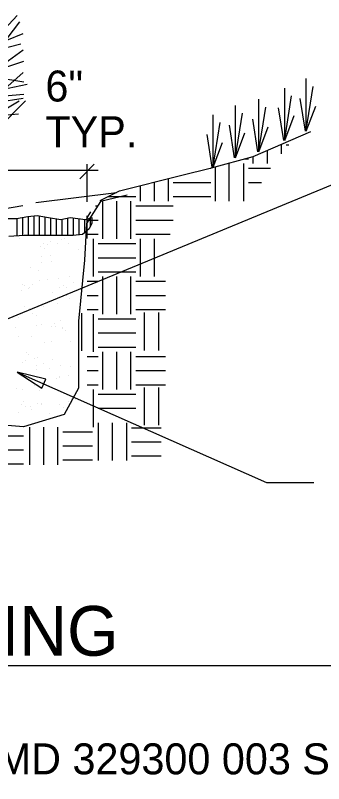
# Model space of a CAD drawing. Extents: x 10082 to 10186, y 10014 to 10052.
# Drawn here: x 10140.43 to 10147.41, y 10014.37 to 10031.75 of the extents above; entities that cross this region are included whole.
import ezdxf

# ---------------------------------------------------------------- set-up
doc = ezdxf.new("R2010")
doc.units = 0
for name, color, linetype in [('Default', 7, 'Continuous'), ('G-ANNO-CELL', 7, 'Continuous'), ('G-ANNO-TEXT', 7, 'Continuous'), ('G-DETL-GRID', 7, 'Continuous'), ('G-DETL-LINE', 7, 'Continuous'), ('G-DETL-OTLN', 7, 'Continuous'), ('G-DETL-PATT', 7, 'Continuous'), ('G-DETL-TEXT', 7, 'Continuous')]:
    doc.layers.add(name, color=color, linetype=linetype)

msp = doc.modelspace()

# ---------------------------------------------------------------- linework, layer by layer
at = {"layer": 'Default'}
for p, q in [((10148.734, 10028.388), (10138.509, 10024.167)), ((10141.886, 10028.058), (10142.213, 10028.385)), ((10142.05, 10027.536), (10142.05, 10028.385)), ((10139.707, 10028.252), (10142.301, 10028.252)), ((10144.838, 10028.297), (10144.857, 10028.297)), ((10140.472, 10023.683), (10146.119, 10021.186)), ((10146.119, 10021.186), (10147.188, 10021.186))]:
    msp.add_line(p, q, dxfattribs=at)
msp.add_lwpolyline([(10141.028, 10023.323), (10141.115, 10023.523), (10140.472, 10023.683)], close=True, dxfattribs=at)
at = {"layer": 'G-ANNO-TEXT'}
msp.add_line((10122.114, 10017.044), (10151.008, 10017.044), dxfattribs=at)
at = {"layer": 'G-DETL-LINE'}
for p, q in [((10140.231, 10031.197), (10140.603, 10031.347)), ((10139.716, 10030.903), (10140.549, 10031.107)), ((10139.938, 10030.496), (10140.603, 10030.975)), ((10139.716, 10030.4), (10140.621, 10030.25)), ((10147.016, 10029.175), (10147.016, 10030.324)), ((10140.267, 10030.106), (10140.698, 10030.196)), ((10146.527, 10028.961), (10146.527, 10030.111)), ((10147.016, 10029.157), (10147.173, 10030.149)), ((10146.527, 10028.944), (10146.685, 10029.935)), ((10139.77, 10029.752), (10140.603, 10029.884)), ((10139.83, 10028.991), (10140.657, 10029.818)), ((10139.991, 10029.513), (10140.513, 10029.824)), ((10145.941, 10028.707), (10145.941, 10029.856)), ((10146.996, 10029.137), (10146.878, 10029.877)), ((10145.412, 10028.569), (10145.412, 10029.719)), ((10145.941, 10028.689), (10146.099, 10029.681)), ((10146.507, 10028.923), (10146.39, 10029.663)), ((10147.016, 10029.137), (10147.23, 10029.701)), ((10144.907, 10028.356), (10144.907, 10029.505)), ((10145.412, 10028.552), (10145.57, 10029.543)), ((10145.921, 10028.669), (10145.804, 10029.409)), ((10146.527, 10028.923), (10146.741, 10029.488)), ((10144.907, 10028.338), (10145.065, 10029.33)), ((10145.392, 10028.531), (10145.275, 10029.271)), ((10145.941, 10028.669), (10146.155, 10029.233)), ((10144.887, 10028.318), (10144.77, 10029.058)), ((10145.412, 10028.531), (10145.626, 10029.096)), ((10144.907, 10028.318), (10145.121, 10028.882)), ((10142.051, 10027.178), (10142.134, 10027.311)), ((10142.246, 10027.445), (10142.301, 10027.445)), ((10142.054, 10026.71), (10142.054, 10027.222))]:
    msp.add_line(p, q, dxfattribs=at)
for points in [[(10137.841, 10030.418), (10139.692, 10030.921), (10140.471, 10031.755)], [(10137.176, 10028.158), (10137.158, 10028.715), (10137.859, 10029.231), (10139.141, 10029.788), (10140.531, 10031.605)], [(10138.098, 10028.733), (10138.302, 10028.937), (10139.063, 10030.196), (10140.621, 10030.718)], [(10138.098, 10028.751), (10138.955, 10029.009), (10140.603, 10030.46)], [(10139.123, 10029.842), (10140.621, 10029.974)], [(10139.452, 10029.435), (10140.495, 10029.53)], [(10140.89, 10027.523), (10142.717, 10027.745)], [(10137.607, 10026.942), (10140.597, 10027.451)]]:
    msp.add_lwpolyline(points, dxfattribs=at)
at = {"layer": 'G-DETL-OTLN'}
for p, q in [((10142.351, 10027.57), (10142.784, 10027.787)), ((10140.153, 10027.159), (10140.452, 10027.159)), ((10140.452, 10027.159), (10140.709, 10027.205)), ((10140.709, 10027.205), (10140.923, 10027.224)), ((10140.923, 10027.224), (10141.18, 10027.182)), ((10141.18, 10027.182), (10141.457, 10027.14)), ((10141.457, 10027.14), (10141.672, 10027.182)), ((10141.672, 10027.182), (10142.013, 10027.14)), ((10142.013, 10027.14), (10142.163, 10027.182)), ((10142.163, 10027.182), (10142.163, 10027.055)), ((10142.163, 10027.055), (10142.098, 10026.925)), ((10141.948, 10026.798), (10141.737, 10026.775)), ((10142.098, 10026.925), (10141.948, 10026.798)), ((10140.624, 10026.775), (10140.283, 10026.755)), ((10140.988, 10026.775), (10140.624, 10026.775)), ((10141.737, 10026.775), (10140.988, 10026.775))]:
    msp.add_line(p, q, dxfattribs=at)
for points in [[(10145.817, 10028.563), (10147.117, 10029.129)], [(10144.867, 10028.304), (10145.817, 10028.563)], [(10144.168, 10028.129), (10144.867, 10028.304)], [(10142.784, 10027.787), (10144.168, 10028.129)], [(10142.956, 10027.686), (10142.357, 10027.547), (10142.04, 10027.044), (10141.992, 10026.215), (10141.854, 10024.835), (10141.854, 10023.321), (10141.53, 10022.722), (10140.614, 10022.448), (10138.96, 10022.583), (10137.624, 10022.539), (10136.198, 10022.539), (10134.778, 10022.631), (10133.4, 10022.539), (10132.292, 10022.539), (10131.603, 10023.091), (10131.513, 10024.284), (10131.375, 10025.343), (10131.148, 10025.251)]]:
    msp.add_lwpolyline(points, dxfattribs=at)
at = {"layer": 'G-DETL-PATT'}
for p, q in [((10146.135, 10028.403), (10146.135, 10028.701)), ((10146.455, 10028.619), (10146.455, 10028.841)), ((10146.561, 10028.829), (10146.619, 10028.829)), ((10145.816, 10028.403), (10145.816, 10028.562)), ((10145.267, 10027.551), (10145.267, 10028.403)), ((10145.603, 10027.551), (10145.603, 10028.403)), ((10145.623, 10028.51), (10145.709, 10028.51)), ((10144.964, 10027.551), (10144.964, 10028.33)), ((10145.709, 10028.297), (10146.204, 10028.297)), ((10143.898, 10027.551), (10143.898, 10028.063)), ((10143.259, 10027.551), (10143.259, 10027.904)), ((10143.579, 10027.551), (10143.579, 10027.983)), ((10144.005, 10027.977), (10144.857, 10027.977)), ((10145.709, 10027.977), (10146.004, 10027.977)), ((10142.527, 10027.658), (10143.153, 10027.658)), ((10144.005, 10027.658), (10144.857, 10027.658)), ((10142.407, 10026.699), (10142.407, 10027.551)), ((10142.727, 10026.699), (10142.727, 10027.551)), ((10143.046, 10026.699), (10143.046, 10027.551)), ((10143.153, 10027.445), (10144.005, 10027.445)), ((10140.466, 10026.766), (10140.466, 10027.162)), ((10140.594, 10026.773), (10140.594, 10027.184)), ((10140.722, 10026.775), (10140.722, 10027.206)), ((10140.85, 10026.775), (10140.85, 10027.218)), ((10140.977, 10026.775), (10140.977, 10027.215)), ((10141.105, 10026.775), (10141.105, 10027.194)), ((10141.233, 10026.775), (10141.233, 10027.174)), ((10141.361, 10026.775), (10141.361, 10027.154)), ((10141.489, 10026.775), (10141.489, 10027.146)), ((10141.616, 10026.775), (10141.616, 10027.171)), ((10141.744, 10026.776), (10141.744, 10027.173)), ((10141.872, 10026.79), (10141.872, 10027.157)), ((10142, 10026.842), (10142, 10027.141)), ((10142.128, 10026.984), (10142.128, 10027.172)), ((10142.054, 10027.125), (10142.301, 10027.125)), ((10143.153, 10027.125), (10144.005, 10027.125)), ((10142.054, 10026.806), (10142.301, 10026.806)), ((10143.153, 10026.806), (10143.932, 10026.806)), ((10140.528, 10026.71), (10140.528, 10026.71)), ((10141.221, 10026.647), (10141.221, 10026.647)), ((10141.466, 10026.674), (10141.466, 10026.674)), ((10141.55, 10026.71), (10141.55, 10026.71)), ((10142.194, 10025.847), (10142.194, 10026.699)), ((10143.259, 10025.847), (10143.259, 10026.699)), ((10143.579, 10025.847), (10143.579, 10026.699)), ((10140.999, 10026.53), (10140.999, 10026.53)), ((10141.068, 10026.584), (10141.068, 10026.584)), ((10141.082, 10026.489), (10141.082, 10026.489)), ((10141.146, 10026.563), (10141.146, 10026.563)), ((10141.382, 10026.596), (10141.382, 10026.596)), ((10141.622, 10026.604), (10141.622, 10026.604)), ((10141.847, 10026.455), (10141.847, 10026.455)), ((10142.301, 10026.593), (10143.153, 10026.593)), ((10141.023, 10026.301), (10141.023, 10026.301)), ((10141.216, 10026.333), (10141.216, 10026.333)), ((10142.301, 10026.273), (10143.153, 10026.273)), ((10141.023, 10026.157), (10141.023, 10026.157)), ((10141.241, 10026.195), (10141.241, 10026.195)), ((10140.761, 10026.04), (10140.761, 10026.04)), ((10140.954, 10025.972), (10140.954, 10025.972)), ((10142.301, 10025.954), (10143.153, 10025.954)), ((10140.966, 10025.764), (10140.966, 10025.764)), ((10141.147, 10025.777), (10141.147, 10025.777)), ((10141.414, 10025.805), (10141.414, 10025.805)), ((10141.644, 10025.858), (10141.644, 10025.858)), ((10142.054, 10025.741), (10142.301, 10025.741)), ((10142.407, 10024.995), (10142.407, 10025.847)), ((10142.727, 10024.995), (10142.727, 10025.847)), ((10143.046, 10024.995), (10143.046, 10025.847)), ((10143.153, 10025.741), (10143.826, 10025.741)), ((10140.582, 10025.677), (10140.582, 10025.677)), ((10140.644, 10025.645), (10140.644, 10025.645)), ((10140.73, 10025.583), (10140.73, 10025.583)), ((10140.741, 10025.603), (10140.741, 10025.603)), ((10140.825, 10025.667), (10140.825, 10025.667)), ((10141.431, 10025.603), (10141.431, 10025.603)), ((10141.52, 10025.653), (10141.52, 10025.653)), ((10141.593, 10025.603), (10141.593, 10025.603)), ((10141.744, 10025.708), (10141.744, 10025.708)), ((10140.571, 10025.523), (10140.571, 10025.523)), ((10141.258, 10025.482), (10141.258, 10025.482)), ((10141.588, 10025.416), (10141.588, 10025.416)), ((10142.054, 10025.421), (10142.301, 10025.421)), ((10143.153, 10025.421), (10143.826, 10025.421)), ((10141.38, 10025.234), (10141.38, 10025.234)), ((10141.652, 10025.352), (10141.652, 10025.352)), ((10140.627, 10025.178), (10140.627, 10025.178)), ((10140.744, 10025.134), (10140.744, 10025.134)), ((10141.071, 10025.171), (10141.071, 10025.171)), ((10142.054, 10025.102), (10142.301, 10025.102)), ((10143.153, 10025.102), (10143.826, 10025.102)), ((10140.501, 10024.911), (10140.501, 10024.911)), ((10140.814, 10025.019), (10140.814, 10025.019)), ((10140.913, 10024.958), (10140.913, 10024.958)), ((10141.931, 10024.167), (10141.931, 10025.019)), ((10142.194, 10024.143), (10142.194, 10024.995)), ((10142.301, 10024.889), (10143.153, 10024.889)), ((10143.354, 10024.176), (10143.354, 10025.029)), ((10143.674, 10024.176), (10143.674, 10025.029)), ((10140.917, 10024.745), (10140.917, 10024.745)), ((10141.014, 10024.751), (10141.014, 10024.751)), ((10141.252, 10024.718), (10141.252, 10024.718)), ((10141.323, 10024.783), (10141.323, 10024.783)), ((10141.328, 10024.727), (10141.328, 10024.727)), ((10141.454, 10024.862), (10141.454, 10024.862)), ((10140.429, 10024.688), (10140.429, 10024.688)), ((10141.493, 10024.663), (10141.493, 10024.663)), ((10141.499, 10024.696), (10141.499, 10024.696)), ((10141.574, 10024.632), (10141.574, 10024.632)), ((10142.301, 10024.569), (10143.153, 10024.569)), ((10140.499, 10024.483), (10140.499, 10024.483)), ((10140.783, 10024.496), (10140.783, 10024.496)), ((10141.091, 10024.356), (10141.091, 10024.356)), ((10141.257, 10024.372), (10141.257, 10024.372)), ((10141.67, 10024.386), (10141.67, 10024.386)), ((10142.301, 10024.25), (10143.153, 10024.25)), ((10140.678, 10024.139), (10140.678, 10024.139)), ((10140.736, 10024.092), (10140.736, 10024.092)), ((10140.927, 10024.008), (10140.927, 10024.008)), ((10142.054, 10024.037), (10142.301, 10024.037)), ((10142.407, 10023.291), (10142.407, 10024.143)), ((10142.727, 10023.291), (10142.727, 10024.143)), ((10143.046, 10023.291), (10143.046, 10024.143)), ((10143.153, 10024.037), (10143.826, 10024.037)), ((10140.597, 10023.898), (10140.597, 10023.898)), ((10140.667, 10023.943), (10140.667, 10023.943)), ((10140.868, 10023.998), (10140.868, 10023.998)), ((10140.911, 10023.832), (10140.911, 10023.832)), ((10141.059, 10023.882), (10141.059, 10023.882)), ((10141.264, 10023.966), (10141.264, 10023.966)), ((10140.912, 10023.747), (10140.912, 10023.747)), ((10141.209, 10023.759), (10141.209, 10023.759)), ((10141.446, 10023.824), (10141.446, 10023.824)), ((10141.679, 10023.801), (10141.679, 10023.801)), ((10142.054, 10023.717), (10142.301, 10023.717)), ((10143.153, 10023.717), (10143.826, 10023.717)), ((10141.354, 10023.533), (10141.354, 10023.533)), ((10141.435, 10023.567), (10141.435, 10023.567)), ((10141.437, 10023.577), (10141.437, 10023.577)), ((10141.627, 10023.611), (10141.627, 10023.611)), ((10140.443, 10023.32), (10140.443, 10023.32)), ((10140.861, 10023.392), (10140.861, 10023.392)), ((10142.054, 10023.398), (10142.301, 10023.398)), ((10143.153, 10023.398), (10143.826, 10023.398)), ((10143.354, 10022.486), (10143.354, 10023.338)), ((10143.674, 10022.486), (10143.674, 10023.338)), ((10140.594, 10023.295), (10140.594, 10023.295)), ((10140.971, 10023.272), (10140.971, 10023.272)), ((10141.61, 10023.188), (10141.61, 10023.188)), ((10142.194, 10022.439), (10142.194, 10023.291)), ((10142.301, 10023.185), (10143.153, 10023.185)), ((10140.613, 10023.021), (10140.613, 10023.021)), ((10140.921, 10022.977), (10140.921, 10022.977)), ((10141.024, 10022.962), (10141.024, 10022.962)), ((10141.029, 10022.972), (10141.029, 10022.972)), ((10141.635, 10023.021), (10141.635, 10023.021)), ((10141.688, 10023.076), (10141.688, 10023.076)), ((10141.782, 10023.058), (10141.782, 10023.058)), ((10140.57, 10022.947), (10140.57, 10022.947)), ((10140.663, 10022.903), (10140.663, 10022.903)), ((10140.767, 10022.906), (10140.767, 10022.906)), ((10140.782, 10022.846), (10140.782, 10022.846)), ((10141.422, 10022.947), (10141.422, 10022.947)), ((10141.511, 10022.891), (10141.511, 10022.891)), ((10142.301, 10022.865), (10143.153, 10022.865)), ((10140.496, 10022.766), (10140.496, 10022.766)), ((10141.2, 10022.748), (10141.2, 10022.748)), ((10140.754, 10021.59), (10140.754, 10022.442)), ((10141.073, 10021.59), (10141.073, 10022.442)), ((10141.393, 10021.59), (10141.393, 10022.442)), ((10142.312, 10021.681), (10142.312, 10022.533)), ((10142.631, 10021.681), (10142.631, 10022.533)), ((10142.951, 10021.681), (10142.951, 10022.533)), ((10141.499, 10022.336), (10142.172, 10022.336)), ((10143.057, 10022.427), (10143.73, 10022.427)), ((10139.936, 10022.245), (10140.608, 10022.245)), ((10143.057, 10022.107), (10143.73, 10022.107)), ((10139.936, 10021.925), (10140.608, 10021.925)), ((10141.499, 10022.016), (10142.172, 10022.016)), ((10143.057, 10021.788), (10143.73, 10021.788)), ((10139.936, 10021.606), (10140.608, 10021.606)), ((10141.499, 10021.697), (10142.172, 10021.697))]:
    msp.add_line(p, q, dxfattribs=at)

# ---------------------------------------------------------------- texts
at = {"layer": 'G-ANNO-CELL'}
msp.add_text('MD 329300 003 Shrub Planting 7/27/18', height=0.7, dxfattribs=at).set_placement((10140.005, 10014.585))
at = {"layer": 'G-DETL-GRID'}
msp.add_text('SHRUB PLANTING', height=1.125, dxfattribs=at).set_placement((10129.561, 10017.268))
at = {"layer": 'G-DETL-TEXT'}
for s, p in [('6" ', (10141.108, 10029.806)), ('TYP.', (10141.108, 10028.773))]:
    msp.add_text(s, height=0.7, dxfattribs=at).set_placement(p)

doc.saveas('drawing.dxf')
